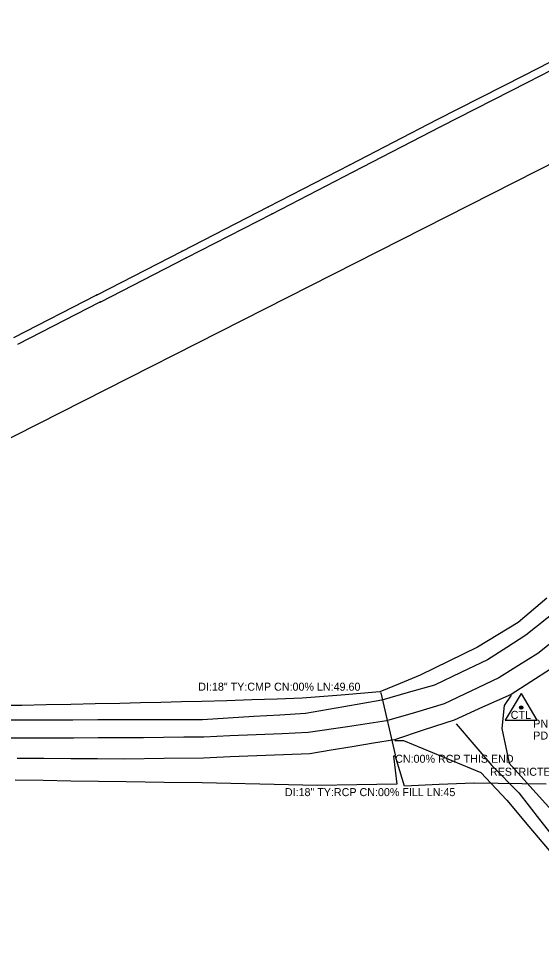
# Model space of a CAD drawing. Extents: x 1707085 to 1720058, y 548761 to 560063.
# Drawn here: x 1711989 to 1712315, y 549372 to 549950 of the extents above; entities that cross this region are included whole.
import ezdxf

# ---------------------------------------------------------------- set-up
doc = ezdxf.new("R2010")
doc.units = 0
for name, color, linetype in [('22', 7, 'Continuous'), ('3', 7, 'Continuous'), ('R_Contour Annot', 7, 'Continuous'), ('S_CROSS_DRAIN_ANNOT', 7, 'Continuous'), ('S_DRG_PT_SYM', 7, 'Continuous'), ('S_EDGE_PAVEMENT', 7, 'Continuous'), ('S_MSC_PT_SYM', 7, 'Continuous'), ('S_PAVEMENT_CROWN', 7, 'Continuous'), ('S_PRIMARY_CTL_ANNOT', 7, 'Continuous'), ('S_SIDE_DRAIN_ANNOT', 7, 'Continuous'), ('S_SURVEY_TEXT_ANNOT', 7, 'Continuous'), ('S_UTILITY_POLE', 7, 'Continuous')]:
    doc.layers.add(name, color=color, linetype=linetype)

msp = doc.modelspace()

# ---------------------------------------------------------------- linework, layer by layer
for points in [[(1712318.76, 549587.45), (1712300.85, 549572.22), (1712288.16, 549564.51), (1712275.47, 549556.8), (1712257.58, 549548.03), (1712239.69, 549539.27), (1712227.09, 549534.04), (1712214.49, 549528.82), (1712190.19, 549526.84), (1712165.89, 549524.87), (1712150.26, 549524.37), (1712134.63, 549523.87), (1712119, 549523.36), (1712103.37, 549522.86), (1712090.57, 549522.57), (1712077.77, 549522.28), (1712064.97, 549522), (1712052.17, 549521.71), (1712036.85, 549521.39), (1712021.52, 549521.07), (1712006.19, 549520.76), (1711990.87, 549520.44), (1711975.92, 549520.28)], [(1712273.07, 549471.86), (1712251.4, 549470.95), (1712229.73, 549470.03), (1712224.01, 549489.05), (1712222.89, 549488.75), (1712225.01, 549471.2), (1712200.14, 549470.84), (1712175.28, 549470.48), (1712157.36, 549470.86), (1712139.43, 549471.24), (1712121.51, 549471.62), (1712103.59, 549472), (1712079.82, 549472.33), (1712056.05, 549472.67), (1712038.77, 549472.93), (1712021.48, 549473.19), (1712004.2, 549473.45), (1711986.91, 549473.71)]]:
    msp.add_lwpolyline(points)
at = {"layer": '22'}
for p, q in [((1712304.76, 549914.22), (1712360.1, 549942.79)), ((1712306.81, 549909.7), (1712362.36, 549938.57)), ((1712250.25, 549886.41), (1712304.76, 549914.22)), ((1712252.58, 549882.06), (1712306.81, 549909.7)), ((1712195.67, 549858.23), (1712250.25, 549886.41)), ((1712197.88, 549853.67), (1712252.58, 549882.06)), ((1712144.83, 549831.99), (1712195.67, 549858.23)), ((1712147.16, 549827.58), (1712197.88, 549853.67)), ((1712090.98, 549804.26), (1712144.83, 549831.99)), ((1712093.49, 549800.04), (1712147.16, 549827.58)), ((1712037.93, 549777.02), (1712090.98, 549804.26)), ((1712040.19, 549772.65), (1712093.49, 549800.04)), ((1712037.48, 549776.74), (1711985.75, 549750.13)), ((1712039.72, 549772.42), (1711988.25, 549745.9))]:
    msp.add_line(p, q, dxfattribs=at)
at = {"layer": '3'}
for p, q in [((1712215.12, 549528.19), (1712223.98, 549489.59)), ((1712273.3, 549472.1), (1712318.27, 549471.46))]:
    msp.add_line(p, q, dxfattribs=at)
at = {"layer": 'R_Contour Annot'}
for p, q in [((1712302.69, 549527.78), (1712292.66, 549511.26)), ((1712302.69, 549527.78), (1712312.52, 549511.26)), ((1712292.66, 549511.26), (1712312.52, 549511.26))]:
    msp.add_line(p, q, dxfattribs=at)
for radius in [1.04, 0.609, 0.344]:
    msp.add_circle((1712302.69, 549519.08), radius, dxfattribs=at)
at = {"layer": 'S_DRG_PT_SYM'}
for points in [[(1712215.12, 549528.19), (1712215.12, 549528.24), (1712215.12, 549528.19), (1712215.07, 549528.19), (1712215.12, 549528.19), (1712215.12, 549528.14), (1712215.12, 549528.19), (1712215.17, 549528.19)], [(1712223.98, 549489.59), (1712223.98, 549489.64), (1712223.98, 549489.59), (1712223.93, 549489.59), (1712223.98, 549489.59), (1712223.98, 549489.54), (1712223.98, 549489.59), (1712224.03, 549489.59)], [(1712273.3, 549472.1), (1712273.3, 549472.15), (1712273.3, 549472.1), (1712273.25, 549472.1), (1712273.3, 549472.1), (1712273.3, 549472.05), (1712273.3, 549472.1), (1712273.35, 549472.1)]]:
    msp.add_lwpolyline(points, dxfattribs=at)
at = {"layer": 'S_EDGE_PAVEMENT'}
for points in [[(1712324.74, 549579.52), (1712305.58, 549564.31), (1712293.62, 549556.65), (1712281.65, 549548.99), (1712265.07, 549541.04), (1712248.48, 549533.1), (1712232.1, 549528.44), (1712215.71, 549523.78), (1712191.89, 549519.6), (1712168.07, 549515.43), (1712151.97, 549514.41), (1712135.87, 549513.4), (1712119.76, 549512.39), (1712103.66, 549511.37), (1712078.83, 549511.38), (1712054, 549511.38), (1712038.41, 549511.34), (1712022.82, 549511.29), (1712007.23, 549511.25), (1711991.65, 549511.21), (1711976.87, 549511.17)], [(1712324.74, 549579.52), (1712305.58, 549564.31), (1712293.62, 549556.65), (1712281.65, 549548.99), (1712265.07, 549541.04), (1712248.48, 549533.1), (1712232.1, 549528.44), (1712215.71, 549523.78), (1712191.89, 549519.6), (1712168.07, 549515.43), (1712151.97, 549514.41), (1712135.87, 549513.4), (1712119.76, 549512.39), (1712103.66, 549511.37), (1712078.83, 549511.38), (1712054, 549511.38), (1712038.41, 549511.34), (1712022.82, 549511.29), (1712007.23, 549511.25), (1711991.65, 549511.21), (1711976.87, 549511.17)], [(1712320.94, 549543.12), (1712308.7, 549535.18), (1712296.46, 549527.24), (1712278.61, 549519.22), (1712260.77, 549511.2), (1712242.17, 549505.09), (1712223.57, 549498.98), (1712210.39, 549496.79), (1712197.21, 549494.6), (1712184.03, 549492.42), (1712170.84, 549490.23), (1712154.24, 549489.56), (1712137.63, 549488.89), (1712121.03, 549488.21), (1712104.42, 549487.54), (1712079.73, 549487.21), (1712055.03, 549486.88), (1712038.29, 549486.97), (1712021.54, 549487.06), (1712004.79, 549487.15), (1711988.04, 549487.23)], [(1712320.94, 549543.12), (1712308.7, 549535.18), (1712296.46, 549527.24), (1712278.61, 549519.22), (1712260.77, 549511.2), (1712242.17, 549505.09), (1712223.57, 549498.98), (1712210.39, 549496.79), (1712197.21, 549494.6), (1712184.03, 549492.42), (1712170.84, 549490.23), (1712154.24, 549489.56), (1712137.63, 549488.89), (1712121.03, 549488.21), (1712104.42, 549487.54), (1712079.73, 549487.21), (1712055.03, 549486.88), (1712038.29, 549486.97), (1712021.54, 549487.06), (1712004.79, 549487.15), (1711988.04, 549487.23)], [(1712296.46, 549526.84), (1712292.01, 549520.42), (1712290.52, 549506), (1712295.1, 549484.36), (1712308.08, 549470.06), (1712321.8, 549454.8), (1712335.53, 549439.55), (1712350.04, 549422.39), (1712364.55, 549405.24), (1712380.17, 549387.13), (1712393.81, 549378.95), (1712408.98, 549375.38), (1712421.46, 549378.78), (1712433.94, 549382.18), (1712451.28, 549391.53), (1712468.62, 549400.89), (1712479.92, 549407.22), (1712491.22, 549413.56), (1712502.51, 549419.9), (1712513.81, 549426.24), (1712531.2, 549435.67), (1712548.58, 549445.1), (1712565.97, 549454.53), (1712583.35, 549463.96)], [(1712223.72, 549498.51), (1712229.13, 549498.44), (1712241.24, 549493.44), (1712253.34, 549488.44), (1712265.45, 549483.43), (1712277.56, 549478.43), (1712293.69, 549461.21), (1712307.52, 549444.74), (1712321.35, 549428.27), (1712335.89, 549411.22), (1712350.42, 549394.17), (1712358.86, 549384.32), (1712367.29, 549374.48), (1712384.89, 549361.9)]]:
    msp.add_lwpolyline(points, dxfattribs=at)
at = {"layer": 'S_MSC_PT_SYM'}
for points in [[(1712304.76, 549914.22), (1712304.76, 549914.27), (1712304.76, 549914.22), (1712304.71, 549914.22), (1712304.76, 549914.22), (1712304.76, 549914.17), (1712304.76, 549914.22), (1712304.81, 549914.22)], [(1712306.81, 549909.7), (1712306.81, 549909.75), (1712306.81, 549909.7), (1712306.76, 549909.7), (1712306.81, 549909.7), (1712306.81, 549909.65), (1712306.81, 549909.7), (1712306.86, 549909.7)], [(1712250.25, 549886.41), (1712250.25, 549886.46), (1712250.25, 549886.41), (1712250.2, 549886.41), (1712250.25, 549886.41), (1712250.25, 549886.36), (1712250.25, 549886.41), (1712250.3, 549886.41)], [(1712252.58, 549882.06), (1712252.58, 549882.11), (1712252.58, 549882.06), (1712252.53, 549882.06), (1712252.58, 549882.06), (1712252.58, 549882.01), (1712252.58, 549882.06), (1712252.63, 549882.06)], [(1712195.67, 549858.23), (1712195.67, 549858.28), (1712195.67, 549858.23), (1712195.62, 549858.23), (1712195.67, 549858.23), (1712195.67, 549858.18), (1712195.67, 549858.23), (1712195.72, 549858.23)], [(1712197.88, 549853.67), (1712197.88, 549853.72), (1712197.88, 549853.67), (1712197.83, 549853.67), (1712197.88, 549853.67), (1712197.88, 549853.62), (1712197.88, 549853.67), (1712197.93, 549853.67)], [(1712144.83, 549831.99), (1712144.83, 549832.04), (1712144.83, 549831.99), (1712144.78, 549831.99), (1712144.83, 549831.99), (1712144.83, 549831.94), (1712144.83, 549831.99), (1712144.88, 549831.99)], [(1712147.16, 549827.58), (1712147.16, 549827.63), (1712147.16, 549827.58), (1712147.11, 549827.58), (1712147.16, 549827.58), (1712147.16, 549827.53), (1712147.16, 549827.58), (1712147.21, 549827.58)], [(1712090.98, 549804.26), (1712090.98, 549804.31), (1712090.98, 549804.26), (1712090.93, 549804.26), (1712090.98, 549804.26), (1712090.98, 549804.21), (1712090.98, 549804.26), (1712091.03, 549804.26)], [(1712093.49, 549800.04), (1712093.49, 549800.09), (1712093.49, 549800.04), (1712093.44, 549800.04), (1712093.49, 549800.04), (1712093.49, 549799.99), (1712093.49, 549800.04), (1712093.54, 549800.04)], [(1712037.48, 549776.74), (1712037.48, 549776.79), (1712037.48, 549776.74), (1712037.43, 549776.74), (1712037.48, 549776.74), (1712037.48, 549776.69), (1712037.48, 549776.74), (1712037.53, 549776.74)], [(1712037.93, 549777.02), (1712037.93, 549777.07), (1712037.93, 549777.02), (1712037.88, 549777.02), (1712037.93, 549777.02), (1712037.93, 549776.97), (1712037.93, 549777.02), (1712037.98, 549777.02)], [(1712039.72, 549772.42), (1712039.72, 549772.47), (1712039.72, 549772.42), (1712039.67, 549772.42), (1712039.72, 549772.42), (1712039.72, 549772.37), (1712039.72, 549772.42), (1712039.77, 549772.42)], [(1712040.19, 549772.65), (1712040.19, 549772.7), (1712040.19, 549772.65), (1712040.14, 549772.65), (1712040.19, 549772.65), (1712040.19, 549772.6), (1712040.19, 549772.65), (1712040.24, 549772.65)], [(1712284.02, 549483.3), (1712284.02, 549483.35), (1712284.02, 549483.3), (1712283.97, 549483.3), (1712284.02, 549483.3), (1712284.02, 549483.25), (1712284.02, 549483.3), (1712284.07, 549483.3)]]:
    msp.add_lwpolyline(points, dxfattribs=at)
at = {"layer": 'S_PAVEMENT_CROWN'}
for points in [[(1712323.33, 549560.97), (1712313.14, 549552.79), (1712300.94, 549545.27), (1712288.73, 549537.75), (1712271.68, 549529.62), (1712254.63, 549521.48), (1712236.63, 549516.09), (1712218.63, 549510.7), (1712194.16, 549507.08), (1712169.69, 549503.45), (1712153.43, 549502.75), (1712137.16, 549502.04), (1712120.9, 549501.34), (1712104.64, 549500.64), (1712092.04, 549500.5), (1712079.45, 549500.36), (1712066.85, 549500.22), (1712054.26, 549500.08), (1712038.69, 549500.07), (1712023.12, 549500.05), (1712007.55, 549500.03), (1711991.98, 549500.01), (1711977.24, 549499.96)], [(1712323.33, 549560.97), (1712313.14, 549552.79), (1712300.94, 549545.27), (1712288.73, 549537.75), (1712271.68, 549529.62), (1712254.63, 549521.48), (1712236.63, 549516.09), (1712218.63, 549510.7), (1712194.16, 549507.08), (1712169.69, 549503.45), (1712153.43, 549502.75), (1712137.16, 549502.04), (1712120.9, 549501.34), (1712104.64, 549500.64), (1712092.04, 549500.5), (1712079.45, 549500.36), (1712066.85, 549500.22), (1712054.26, 549500.08), (1712038.69, 549500.07), (1712023.12, 549500.05), (1712007.55, 549500.03), (1711991.98, 549500.01), (1711977.24, 549499.96)], [(1712262.08, 549508.97), (1712273.19, 549495.92), (1712284.3, 549482.88), (1712301.14, 549465.86), (1712314.12, 549449.22), (1712327.1, 549432.57), (1712342.27, 549416.46), (1712357.44, 549400.34), (1712365.03, 549390.24), (1712372.63, 549380.14), (1712390.32, 549370.7), (1712406.74, 549363.12), (1712422.56, 549368.89), (1712438.39, 549374.65), (1712455.94, 549383.35), (1712473.5, 549392.05), (1712493.73, 549403.76), (1712513.96, 549415.46), (1712532.63, 549425.37), (1712551.3, 549435.29), (1712569.98, 549445.2), (1712588.65, 549455.12)]]:
    msp.add_lwpolyline(points, dxfattribs=at)
at = {"layer": 'S_UTILITY_POLE'}
msp.add_lwpolyline([(1711064.39, 549251.72), (1711313.01, 549347.35), (1711526.73, 549455.46), (1711746.33, 549566.96), (1712411.7, 549904.79), (1712500.91, 549949.57)], dxfattribs=at)

# ---------------------------------------------------------------- texts
at = {"layer": 'R_Contour Annot'}
msp.add_text('CTL', height=5, rotation=360, dxfattribs=at).set_placement((1712296.11, 549512))
at = {"layer": 'S_CROSS_DRAIN_ANNOT'}
for s, p in [('DI:18" TY:CMP CN:00% LN:49.60', (1712101.09, 549529.61)), ('CN:00% RCP THIS END', (1712223.98, 549484.59))]:
    msp.add_text(s, height=5, dxfattribs=at).set_placement(p)
at = {"layer": 'S_PRIMARY_CTL_ANNOT'}
for s, p in [('PN:4', (1712310.19, 549506.58)), ('PD:STD AHTD MON. STAMPED PN:4 JONESBORO', (1712310.19, 549499.08))]:
    msp.add_text(s, height=5, dxfattribs=at).set_placement(p)
at = {"layer": 'S_SIDE_DRAIN_ANNOT'}
msp.add_text('DI:18" TY:RCP CN:00% FILL LN:45', height=5, dxfattribs=at).set_placement((1712155.16, 549463.74))
at = {"layer": 'S_SURVEY_TEXT_ANNOT'}
msp.add_text('RESTRICTED PRVTE APORT RD', height=5, dxfattribs=at).set_placement((1712283.17, 549476.47))

doc.saveas('drawing.dxf')
